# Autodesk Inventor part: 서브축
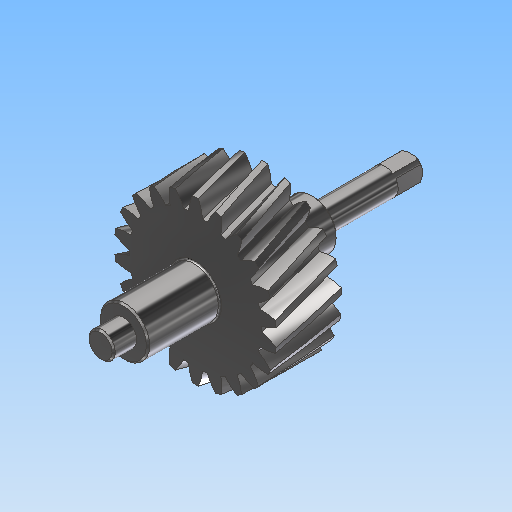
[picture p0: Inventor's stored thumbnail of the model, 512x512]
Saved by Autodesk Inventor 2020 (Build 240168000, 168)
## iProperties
CustomPartVersion: 1
Created: 2017-11
Part Number: 서브축
Material: 강철, 탄소
Document SubType Name: Modeling
Designer: mduedu
Categories: <?xml version="1.0" encoding="UTF-16"?> <MemberInstance><Categories><FamilyTemplate><FamilyTemplateParameter ValueType="xs:double" Id="1" ObjectReferenceKey="da
Density: 1 g/cm^3
Appearance: 반광택
Author: mduedu
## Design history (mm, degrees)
sketch "Sketch1"
  geometry: C1 r 24.776 at (0, 0)
  constraints: 1 centre point
  dimensions: "d0" = 49.55215 diameter of C1 (= da_da)
extrude "Extrusion1" new body sketch "Sketch1" distance "d1" = -20 (= da_b); taper "d2" = 0 deg
workplane "Work Plane2"
sketch "Sketch2"
  geometry: C1 r 24.776 at (0, 0) reference; C2 r 22.776 at (0, 0)
  constraints: 1 centre point, 1 coincident
  dimensions: "d3" = 45.55215 diameter of C2 (= da_dw)
feature "피치 지름" sketch "Sketch2" dims "d4" = 10, "d5" = 0
workplane "Work Plane8"
workplane "Work Plane9"
feature "스퍼 기어" dims "da_b" = -20, "da_d" = 45.55215, "da_aw" = 54.86964, "da_da" = 49.55215, "da_df" = 40.55215, "da_dw" = 45.55215, angle "da_beta" = 15 deg, "da_lefttooth" = 10, "da_righttooth" = 0
sketch "스케치3"
  geometry: C1 r 7.5 at (0, 0); 1 further point
  constraints: 1 centre point, 1 coincident
  dimensions: "d49" = 15 diameter of C1
extrude "돌출2" join sketch "스케치3" distance "d50" = 22; taper "d51" = 0 deg
sketch "스케치4"
  geometry: C1 r 4 at (0, 0); 1 further point
  constraints: 1 centre point, 1 coincident
  dimensions: "d52" = 8 diameter of C1
extrude "돌출3" join sketch "스케치4" distance "d53" = 7; taper "d54" = 0 deg
sketch "스케치5"
  geometry: C1 r 7.5 at (0, 0); 1 further point
  constraints: 1 centre point, 1 coincident
  dimensions: "d55" = 15 diameter of C1
extrude "돌출4" join sketch "스케치5" distance "d56" = 16; taper "d57" = 0 deg
sketch "스케치6"
  geometry: C1 r 4 at (0, 0); 1 further point
  constraints: 1 centre point, 1 coincident
  dimensions: "d58" = 8 diameter of C1
extrude "돌출5" join sketch "스케치6" distance "d59" = 30; taper "d60" = 0 deg
chamfer "모따기1" distance "d61" = 0.5; stored, may be unused: second distance "d62" = 2, angle "d63" = 45 deg
fillet "모깎기1" dims "d64" = 0.5
sketch "스케치7"
  geometry: L1 (-3.25, -3.25)-(3.25, -3.25); L2 (3.25, -3.25)-(3.25, 3.25); L3 (3.25, 3.25)-(-3.25, 3.25); L4 (-3.25, 3.25)-(-3.25, -3.25); L5 (-3.25, -3.25)-(3.25, 3.25); L6 (3.25, -3.25)-(-3.25, 3.25); L7 (-5, -5)-(5, -5); L8 (5, -5)-(5, 5); L9 (5, 5)-(-5, 5); L10 (-5, 5)-(-5, -5); L11 (-5, -5)-(5, 5); L12 (5, -5)-(-5, 5); 1 further point
  constraints: 24 end point, 4 midpoint, 4 parallel, 2 horizontal, 2 perpendicular
  dimensions: "d65" = 6.5 distance of L3.end L2.end; "d66" = 6.5 distance of L2.end L1.end; "d67" = 10 distance of L9.end L8.end; "d68" = 10 distance of L8.end L7.end
extrude "돌출6" cut sketch "스케치7" distance "d69" = 8; taper "d70" = 0 deg
body "Solid1"
body "Srf1"
other parameters: "d16" = 54.86964 (= da_aw), "d17" = 0, "d34" = 1.428 (computed from da_z), "d39" = 0, "d41" = 0, "d43" = 54.86964 (= da_aw), "d46" = 54.86964 (= da_aw), "d47" = 0, "d48" = 0
